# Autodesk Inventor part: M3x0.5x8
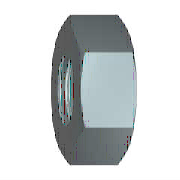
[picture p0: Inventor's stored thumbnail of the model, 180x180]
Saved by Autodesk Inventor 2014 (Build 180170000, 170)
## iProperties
Created: 2009-02
Part Number: M3x0.5x8
Material: 강, 연강
Description: 6각 너트 및 6각 가는 너트
Document SubType Name: Modeling
Standard: KS B 1012
Designer: KYOUNG IL JANG
Standards Organization: KS
Language: ko-KR
Size Designation: C M8
Categories: <MemberInstance><Categories><Category DisplayName="조임쇠" InternalName="e4da775c-781d-43d5-af7c-5136215cf5a6" Mnemonic="FSTN"><Category DisplayName="너트" InternalN
Density: 1 g/cm^3
Vendor: CBT Solutions
Appearance: 강철
Company: 한국ATC센터
IsCustomPart: 0
Author: KYOUNG IL JANG
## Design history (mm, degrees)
sketch "스케치1"
  geometry: L1 (-7.506, 0)-(-3.753, 6.5); L2 (-3.753, 6.5)-(3.753, 6.5); L3 (3.753, 6.5)-(7.506, 0); L4 (7.506, 0)-(3.753, -6.5); L5 (3.753, -6.5)-(-3.753, -6.5); L6 (-3.753, -6.5)-(-7.506, 0); 2 further points
  constraints: 12 end point, 1 coincident, 1 horizontal, 11 other
  dimensions: "d0" = 15.01111 distance of L3.end L1.start (= 1.1547 x SW)
extrude "본체" new body sketch "스케치1" distance "d1" = 7.9 (= KOH); taper "d2" = 0 deg
sketch "스케치2"
  geometry: L1 (0, 3.753)-(0, 7.506) reference; L2 (0, 7.506)-(7.9, 7.506) reference; L3 (7.9, 3.753)-(7.9, 7.506) reference; L4 (-1.58, 0)-(9.48, 0) reference; L5 (0.581, 7.506)-(0, 6.5); L6 (7.319, 7.506)-(7.9, 6.5)
  constraints: 4 end point, 4 point on line
  dimensions: "d3" = 30 deg angle of L1 L5 (= ANG1); "d4" = 30 deg angle of L3 L6 (= ANG2); "d5" = 13 diameter of L5.end L4 (= SW0); "d6" = 13 diameter of L6.end L4 (= SW01)
revolve "모따기1" sketch "스케치2" stored, may be unused: angle "d7" = 90 deg
sketch "스케치3"
  geometry: A1 r 6.5 centre (0, 0) between (-3.25, -5.629) and (3.25, -5.629) reference; 1 further point
  constraints: 1 coincident
hole "스레드" sketch "스케치3" at (0, 0) diameter "d25" = 6.647; stored, may be unused: countersink angle "d29" = 82 deg, drill point angle "d31" = 118 deg; dims "d26" = 6, "d27" = 4, "d28" = 2, "d30" = 8
workaxis "Work Axis1"
workplane "Work Plane1"
body "Solid1"
chamfer "모따기2" distance "d8" = 0.67658 (= -0.5 x GD1 + 0.5 x NND); stored, may be unused: angle "d9" = 30 deg, second distance "d40" = 0.67658 (= -0.5 x GD1 + 0.5 x NND)
chamfer "모따기3" distance "d10" = 0.67658 (= -0.5 x GD1 + 0.5 x NND); stored, may be unused: angle "d11" = 30 deg, second distance "d41" = 0.67658 (= -0.5 x GD1 + 0.5 x NND)
other parameters: "ANG1" = 30 deg [user parameter; used in 1 equation term], "ANG2" = 30 deg [user parameter; used in 1 equation term], "NND" = 8 [user parameter; used in 4 equation terms], "KOH" = 7.9 [user parameter; used in 1 equation term], "SW" = 13 [user parameter; used in 4 equation terms], "SW0" = 13 (= SW) [user parameter; used in 1 equation term], "SW01" = 13 (= SW) [user parameter; used in 1 equation term], "GD1" = 6.64684 (computed from THREADDIA, PTC, TOA) [user parameter; used in 4 equation terms], "d13" = 0, "d14" = 0, "d39" = 0, "d42" = 0, "GUL" = 0.67658 (= 0.541266 x PTC) [user parameter], "TPU" = 8 (computed from PTC) [user parameter], "THREADDIA" = 8 [user parameter; used in 1 equation term], "TOA" = 30 deg [user parameter; used in 1 equation term], "PTC" = 1.25 [user parameter; used in 4 equation terms], "E0" = 15.015 (= 1.155 x SW) [user parameter], "GAL" = 0.67658 (= 0.541266 x PTC) [user parameter]
